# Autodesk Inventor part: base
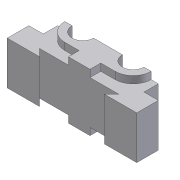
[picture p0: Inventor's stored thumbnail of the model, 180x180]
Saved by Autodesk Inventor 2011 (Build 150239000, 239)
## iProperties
Created: 2009-05
Part Number: base
Document SubType Name: Modeling
Designer: Sham
Density: 1 g/cm^3
Author: Sham
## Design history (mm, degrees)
sketch "Sketch1"
  geometry: L1 (0, 0)-(27.5, 0); L2 (27.5, 0)-(22.5, -5); L3 (22.5, -5)-(45, -5); L4 (45, -5)-(45, 10); L5 (45, 10)-(35, 10); L6 (35, 10)-(35, 20); L7 (35, 20)-(-35, 20); L8 (-35, 20)-(-35, 10); L9 (-35, 10)-(-45, 10); L10 (-45, 10)-(-45, -5); L11 (-45, -5)-(-22.5, -5); L12 (-22.5, -5)-(-27.5, 0); L13 (-27.5, 0)-(0, 0); 1 further point
  constraints: 26 end point, 9 perpendicular, 5 equal length, 2 horizontal, 1 coincident, 1 other
  dimensions: "d1" = 15 distance of L9.end L10.end; "d2" = 5 distance between parallel lines of L11 L13; "d3" = 10 distance of L5.end L6.end; "d4" = 22.5 distance of L2.end L3.end; "d5" = 45 distance of L2.end L11.end; "d6" = 90 distance between parallel lines of L4 L10 (derived); "d7" = 5 horizontal distance of L1.end L2.end; "d15" = 70 distance of L6.end L7.end; "d16" = 35 distance from line of L8 point (0, 0)
extrude "Extrusion1" new body sketch "Sketch1" stored distance "d8" = 30; taper "d9" = 0 deg
sketch "Sketch2"
  geometry: L1 (-7.5, 0)-(-7.5, 7.5); L2 (-7.5, 7.5)-(-17.5, 7.5); L3 (7.5, 7.5)-(17.5, 7.5); L4 (7.5, 0)-(7.5, 7.5); L5 (-7.5, 0)-(7.5, 0); L6 (35, 20)-(-35, 20) reference; L7 (-30, 20)-(30, 20); A1 r 12.5 centre (-17.5, 20) between (-30, 20) and (-17.5, 7.5); A2 r 12.5 centre (17.5, 20) between (17.5, 7.5) and (30, 20); 2 further points
  constraints: 12 end point, 4 point on circle, 3 perpendicular, 2 centre point, 2 horizontal, 2 point on line, 2 tangent, 1 coincident, 1 collinear, 1 horizontal alignment, 1 midpoint, 1 other
  dimensions: "d10" = 15 distance of L1.start L4.start; "d11" = 35 distance of A2.centre A1.centre; "d12" = 12.5 radius of A1; "d13" = 12.5 radius of A2; "d14" = 7.5 distance of L1.start L1.end
extrude "Extrusion2" join sketch "Sketch2" stored distance "d17" = 40; taper "d18" = 0 deg
sketch "Sketch3"
  geometry: L1 (10, 20)-(10.397, 20); L2 (10, 20)-(25, 20); L3 (-25, 20)-(-10, 20); L4 (-30, 20)-(30, 20) reference; A1 r 7.5 centre (-17.5, 20) between (-25, 20) and (-10, 20); A2 r 7.5 centre (17.5, 20) between (10, 20) and (25, 20); A3 r 12.5 centre (17.5, 20) between (17.5, 7.5) and (30, 20) reference; A4 r 12.5 centre (-17.5, 20) between (-30, 20) and (-17.5, 7.5) reference; 2 further points
  constraints: 6 end point, 4 point on circle, 3 coincident, 2 centre point, 2 horizontal, 2 midpoint, 2 point on line, 1 equal radius
  dimensions: "d19" = 15 diameter of A1; "d53" = 7.5 radius of A2 (derived); "d54" = 35 distance of A1.centre A3.centre (derived)
extrude "Extrusion3" cut sketch "Sketch3" distance "d24" = 40; taper "d25" = 0 deg
hole "Hole1" diameter "d28" = 4.5; stored, may be unused: countersink angle "d32" = 90 deg, drill point angle "d34" = 118 deg; dims "d26" = 30, "d27" = 5, "d29" = 6, "d30" = 4, "d31" = 2, "d33" = 15
pattern_linear "Rectangular Pattern1" dims "d37" = 30
hole "Hole2" diameter "d40" = 4.5; stored, may be unused: countersink angle "d44" = 90 deg, drill point angle "d46" = 118 deg; dims "d38" = 5, "d39" = 7.5, "d41" = 6, "d42" = 4, "d43" = 2, "d45" = 15
pattern_linear "Rectangular Pattern2" dims "d49" = 15
body "Solid1"
